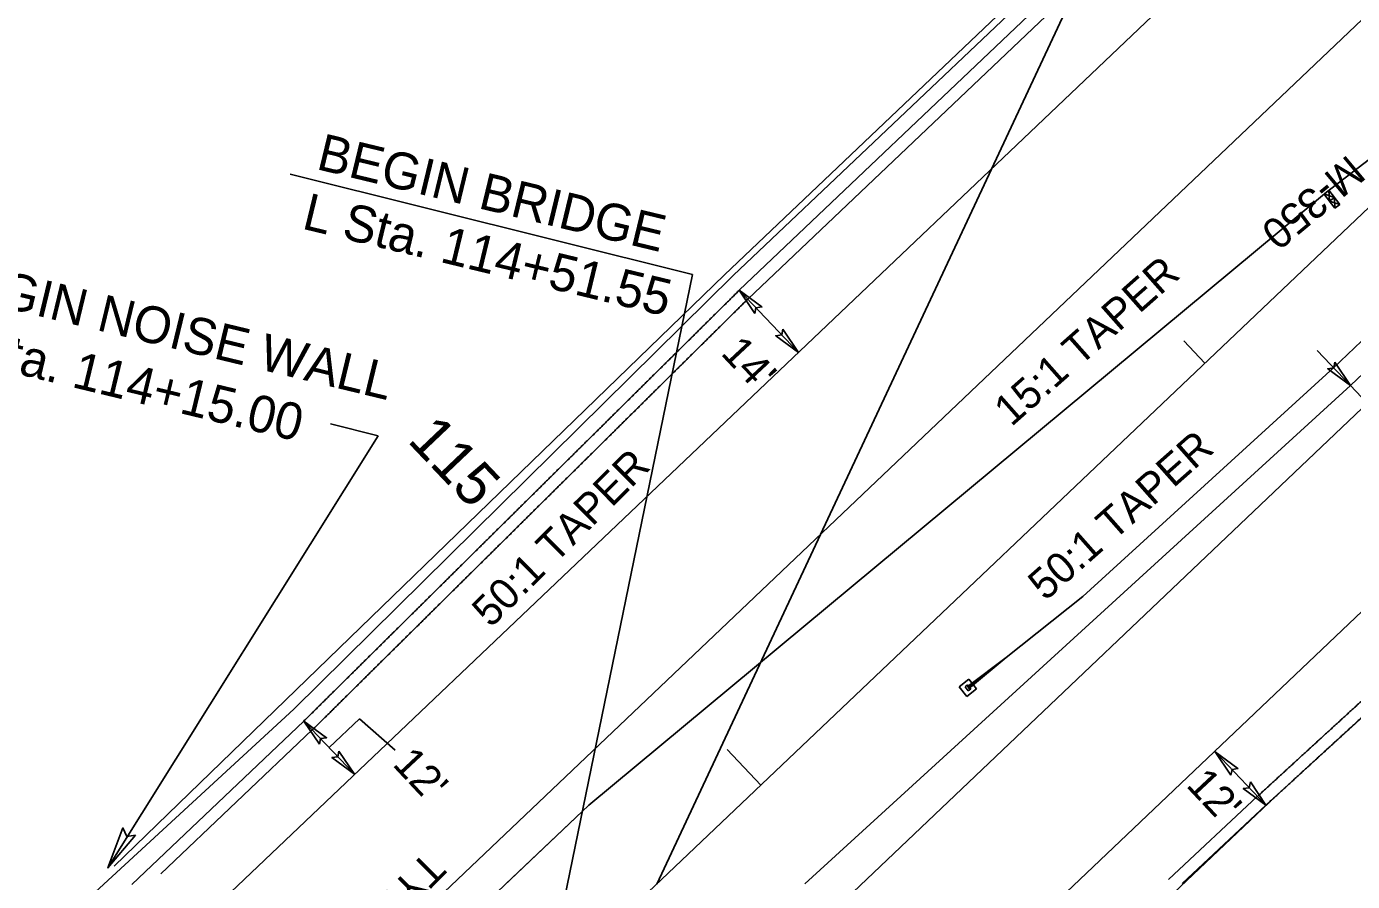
# Model space of a CAD drawing. Extents: x 2389099 to 2405615, y 552200 to 573532.
# Drawn here: x 2397828.9 to 2398045.4, y 559553.6 to 559693.2 of the extents above; entities that cross this region are included whole.
import ezdxf

# ---------------------------------------------------------------- set-up
doc = ezdxf.new("R2010")
doc.units = 0
for name, color, linetype in [('Old_Level_11', 7, 'Continuous'), ('Prop Cable Guiderail Anchor Unit CELL', 7, 'Continuous'), ('Prop Cable Guiderail Double Face', 7, 'Continuous'), ('Prop Conc Barrier Precast Reinforced Single Face', 7, 'Continuous'), ('Prop Conc Expressway Gutter', 7, 'Continuous'), ('Prop Dimension', 7, 'Continuous'), ('Prop Dimension Text', 7, 'Continuous'), ('Prop EOT', 7, 'Continuous'), ('Prop GRAU M350 Approach CELL', 7, 'Continuous'), ('Prop Guardrail', 7, 'Continuous'), ('Prop Horizontal Alignment', 7, 'Continuous'), ('Prop Horizontal Alignment Curve and Spiral Data', 7, 'Continuous'), ('Prop Horizontal Alignment Tick Large', 7, 'Continuous'), ('Prop Horizontal Alignment Tick Small', 7, 'Continuous'), ('Prop Lane Lines', 7, 'Continuous'), ('Prop Noise Wall', 7, 'Continuous')]:
    doc.layers.add(name, color=color, linetype=linetype)

# ---------------------------------------------------------------- blocks, each defined once
blk = doc.blocks.new('TERM')
at = {"layer": 'Old_Level_11'}
blk.add_lwpolyline([(-0.01375, 0.00225), (0, 0), (-0.01375, -0.0025), (-0.012, 0)], close=True, dxfattribs=at)

msp = doc.modelspace()

# ---------------------------------------------------------------- linework, layer by layer
at = {"layer": 'Prop Cable Guiderail Anchor Unit CELL'}
for p, q in [((2398001.36, 559600.11), (2397988.84, 559590.16)), ((2397988.84, 559590.16), (2397982.46, 559585.36)), ((2397988.84, 559590.16), (2397982.57, 559585.18)), ((2397988.84, 559590.16), (2397982.69, 559585.03)), ((2397988.84, 559590.16), (2397988.84, 559590.16)), ((2397981.17, 559585.34), (2397982.73, 559586.59)), ((2397983.98, 559585.02), (2397982.73, 559586.59)), ((2397982.41, 559583.78), (2397981.17, 559585.34)), ((2397982.12, 559585.35), (2397982.51, 559585.66)), ((2397982.64, 559584.7), (2397982.12, 559585.35)), ((2397982.41, 559583.78), (2397983.98, 559585.02)), ((2397983.03, 559585.01), (2397982.51, 559585.66)), ((2397982.64, 559584.7), (2397983.03, 559585.01))]:
    msp.add_line(p, q, dxfattribs=at)
at = {"layer": 'Prop Cable Guiderail Double Face'}
for p, q in [((2398042.26, 559637.46), (2398085.41, 559678.49)), ((2398001.36, 559600.11), (2398042.32, 559637.52))]:
    msp.add_line(p, q, dxfattribs=at)
at = {"layer": 'Prop Conc Barrier Precast Reinforced Single Face'}
for p, q in [((2397944.28, 559652.51), (2398828.89, 560492.26)), ((2397872.55, 559581.72), (2397944.28, 559652.51)), ((2397824.8, 559537.74), (2397872.55, 559581.72))]:
    msp.add_line(p, q, dxfattribs=at)
at = {"layer": 'Prop Conc Expressway Gutter'}
for p, q in [((2397946.63, 559648.66), (2398491.55, 560166.72)), ((2397875.55, 559578.32), (2397850.83, 559554.82)), ((2398029.88, 559567.49), (2398015.3, 559553.9))]:
    msp.add_line(p, q, dxfattribs=at)
for points in [[(2397911.12, 559613.52), (2397911.61, 559614), (2397912.08, 559614.47), (2397912.57, 559614.95), (2397913.04, 559615.42), (2397913.53, 559615.9), (2397914, 559616.37), (2397914.49, 559616.85), (2397914.97, 559617.33), (2397915.45, 559617.8), (2397915.93, 559618.28), (2397916.41, 559618.75), (2397916.89, 559619.23), (2397917.37, 559619.7), (2397917.85, 559620.18), (2397918.33, 559620.65), (2397918.81, 559621.13), (2397919.29, 559621.6), (2397919.77, 559622.08), (2397920.25, 559622.55), (2397920.73, 559623.02), (2397921.21, 559623.5), (2397921.69, 559623.97), (2397922.17, 559624.45), (2397922.66, 559624.93), (2397923.13, 559625.4), (2397923.62, 559625.88), (2397924.09, 559626.35), (2397924.58, 559626.83), (2397925.05, 559627.3), (2397925.53, 559627.78), (2397926.02, 559628.26), (2397926.49, 559628.73), (2397926.98, 559629.21), (2397927.45, 559629.68), (2397927.94, 559630.16), (2397928.41, 559630.63), (2397928.9, 559631.11), (2397929.38, 559631.59), (2397929.86, 559632.06), (2397930.34, 559632.54), (2397930.82, 559633.01), (2397931.3, 559633.49), (2397931.78, 559633.96), (2397932.26, 559634.44), (2397932.74, 559634.91), (2397933.22, 559635.39), (2397933.7, 559635.86), (2397934.18, 559636.34), (2397934.66, 559636.81), (2397935.14, 559637.29), (2397935.62, 559637.76), (2397936.11, 559638.24), (2397936.58, 559638.71), (2397937.07, 559639.19), (2397937.54, 559639.66), (2397938.03, 559640.14), (2397938.5, 559640.61), (2397938.99, 559641.09), (2397939.46, 559641.56), (2397939.95, 559642.04), (2397940.43, 559642.52), (2397940.91, 559642.99), (2397941.39, 559643.47), (2397941.87, 559643.94), (2397942.35, 559644.42), (2397942.83, 559644.89), (2397943.31, 559645.37), (2397943.79, 559645.85), (2397944.27, 559646.32), (2397944.75, 559646.8), (2397945.23, 559647.27), (2397945.71, 559647.75), (2397946.67, 559648.7)], [(2397875.58, 559578.34), (2397876.06, 559578.82), (2397876.54, 559579.29), (2397877.02, 559579.77), (2397877.5, 559580.24), (2397877.98, 559580.72), (2397878.46, 559581.19), (2397878.94, 559581.67), (2397879.42, 559582.15), (2397879.9, 559582.62), (2397880.38, 559583.1), (2397880.86, 559583.57), (2397881.34, 559584.05), (2397881.82, 559584.52), (2397882.3, 559585), (2397882.79, 559585.48), (2397883.26, 559585.95), (2397883.74, 559586.43), (2397884.22, 559586.9), (2397884.7, 559587.38), (2397885.18, 559587.85), (2397885.66, 559588.33), (2397886.14, 559588.8), (2397886.62, 559589.28), (2397887.11, 559589.76), (2397887.58, 559590.23), (2397888.07, 559590.71), (2397888.54, 559591.18), (2397889.03, 559591.66), (2397889.5, 559592.13), (2397889.99, 559592.6), (2397890.47, 559593.08), (2397890.95, 559593.55), (2397891.43, 559594.03), (2397891.91, 559594.5), (2397892.39, 559594.98), (2397892.87, 559595.45), (2397893.35, 559595.93), (2397893.83, 559596.41), (2397894.31, 559596.88), (2397894.79, 559597.36), (2397895.27, 559597.83), (2397895.75, 559598.31), (2397896.23, 559598.78), (2397896.71, 559599.26), (2397897.2, 559599.74), (2397897.67, 559600.21), (2397898.16, 559600.69), (2397898.63, 559601.16), (2397899.12, 559601.64), (2397899.59, 559602.11), (2397900.08, 559602.59), (2397900.56, 559603.07), (2397901.04, 559603.54), (2397901.52, 559604.02), (2397902, 559604.49), (2397902.48, 559604.97), (2397902.96, 559605.44), (2397903.44, 559605.92), (2397903.91, 559606.39), (2397904.4, 559606.86), (2397904.88, 559607.34), (2397905.36, 559607.81), (2397905.84, 559608.29), (2397906.32, 559608.76), (2397906.8, 559609.24), (2397907.28, 559609.71), (2397907.76, 559610.19), (2397908.24, 559610.67), (2397908.72, 559611.14), (2397909.2, 559611.62), (2397909.68, 559612.09), (2397910.16, 559612.57), (2397910.64, 559613.04), (2397911.12, 559613.52)], [(2398029.89, 559567.5), (2398030.39, 559567.96), (2398030.88, 559568.41), (2398031.39, 559568.87), (2398031.88, 559569.33), (2398032.38, 559569.79), (2398032.88, 559570.24), (2398033.38, 559570.7), (2398033.88, 559571.16), (2398034.37, 559571.61), (2398034.87, 559572.07), (2398035.37, 559572.52), (2398035.87, 559572.98), (2398036.36, 559573.44), (2398036.86, 559573.9), (2398037.36, 559574.36), (2398037.86, 559574.81), (2398038.36, 559575.27), (2398038.85, 559575.72), (2398039.36, 559576.18), (2398039.85, 559576.63), (2398040.35, 559577.09), (2398040.84, 559577.55), (2398041.35, 559578), (2398041.85, 559578.46), (2398042.34, 559578.92), (2398042.84, 559579.38), (2398043.34, 559579.83), (2398043.84, 559580.29), (2398044.33, 559580.74), (2398044.83, 559581.2), (2398045.33, 559581.66), (2398045.83, 559582.11), (2398046.33, 559582.57), (2398046.82, 559583.03), (2398047.33, 559583.49), (2398047.82, 559583.94), (2398048.32, 559584.4), (2398048.82, 559584.86), (2398049.32, 559585.31), (2398049.82, 559585.77), (2398050.31, 559586.22), (2398050.81, 559586.68), (2398051.31, 559587.14), (2398051.81, 559587.6), (2398052.31, 559588.05), (2398052.8, 559588.51), (2398053.3, 559588.97), (2398053.8, 559589.42), (2398054.3, 559589.88), (2398054.79, 559590.33), (2398055.3, 559590.79), (2398055.8, 559591.25), (2398056.29, 559591.7), (2398056.79, 559592.16), (2398057.29, 559592.62), (2398057.79, 559593.08), (2398058.28, 559593.53), (2398058.78, 559593.99), (2398059.28, 559594.44), (2398059.78, 559594.9), (2398060.28, 559595.36), (2398060.77, 559595.81), (2398061.27, 559596.27), (2398061.77, 559596.73), (2398062.27, 559597.19), (2398062.76, 559597.64), (2398063.26, 559598.1), (2398063.77, 559598.56), (2398064.26, 559599.01), (2398064.76, 559599.47), (2398065.26, 559599.92), (2398065.76, 559600.38), (2398066.25, 559600.84), (2398066.75, 559601.29)]]:
    msp.add_spline(points, degree=3, dxfattribs=at)
at = {"layer": 'Prop Dimension'}
for p, q in [((2397931.78, 559553.13), (2398012.75, 559726.19)), ((2397937.64, 559652.66), (2397871.95, 559669.08)), ((2397913.68, 559535.92), (2397937.64, 559652.66)), ((2397954.9, 559639.96), (2397945.25, 559650.11)), ((2398039.58, 559640.28), (2398045.01, 559634.57)), ((2398045.01, 559634.57), (2398047.77, 559631.67)), ((2397878.52, 559628.28), (2397886.31, 559626.33)), ((2397886.31, 559626.33), (2397842.18, 559555.78)), ((2397882.44, 559571.07), (2397874.17, 559579.77)), ((2397883.24, 559580.11), (2397878.29, 559575.43)), ((2397889.06, 559575.02), (2397883.24, 559580.11)), ((2398031.24, 559566.03), (2398022.97, 559574.73))]:
    msp.add_line(p, q, dxfattribs=at)
for points in [[(2397947.79, 559646.31), (2397945.25, 559650.11), (2397948.95, 559647.38), (2397947.98, 559647.24)], [(2397952.36, 559643.76), (2397954.9, 559639.96), (2397951.2, 559642.69), (2397952.18, 559642.82)], [(2398042.47, 559638.36), (2398045.01, 559634.57), (2398041.32, 559637.29), (2398042.29, 559637.43)], [(2397876.71, 559575.97), (2397874.17, 559579.77), (2397877.87, 559577.04), (2397876.89, 559576.9)], [(2397879.9, 559574.86), (2397882.44, 559571.07), (2397878.74, 559573.8), (2397879.71, 559573.93)], [(2398025.51, 559570.93), (2398022.97, 559574.73), (2398026.67, 559572), (2398025.7, 559571.86)], [(2398028.7, 559569.82), (2398031.24, 559566.03), (2398027.54, 559568.76), (2398028.52, 559568.89)]]:
    msp.add_lwpolyline(points, close=True, dxfattribs=at)
at = {"layer": 'Prop EOT'}
for p, q in [((2397075.71, 558804.1), (2398839.56, 560481.03)), ((2397092.24, 558786.7), (2398856.1, 560463.63)), ((2398045.01, 559634.57), (2398885.04, 560433.19)), ((2397732.72, 559332.14), (2398887.8, 560430.29)), ((2397749.26, 559314.75), (2398904.33, 560412.9)), ((2397945.25, 559650.11), (2398525.64, 560201.89)), ((2398041.1, 559666.14), (2398071.06, 559689.11)), ((2397920.68, 559566.03), (2398041.1, 559666.14)), ((2397955.93, 559553.19), (2398045.01, 559634.57)), ((2397874.17, 559579.77), (2397846.1, 559553.08)), ((2397907.09, 559553.11), (2397920.68, 559566.03)), ((2398031.24, 559566.03), (2398017.53, 559553.24))]:
    msp.add_line(p, q, dxfattribs=at)
for points in [[(2397909.72, 559614.94), (2397910.2, 559615.42), (2397910.68, 559615.89), (2397911.16, 559616.37), (2397911.64, 559616.84), (2397912.12, 559617.32), (2397912.6, 559617.79), (2397913.08, 559618.27), (2397913.56, 559618.75), (2397914.04, 559619.22), (2397914.52, 559619.7), (2397915, 559620.17), (2397915.48, 559620.65), (2397915.96, 559621.12), (2397916.44, 559621.6), (2397916.93, 559622.08), (2397917.4, 559622.55), (2397917.89, 559623.03), (2397918.36, 559623.5), (2397918.85, 559623.98), (2397919.32, 559624.45), (2397919.81, 559624.92), (2397920.28, 559625.4), (2397920.77, 559625.87), (2397921.25, 559626.35), (2397921.73, 559626.82), (2397922.21, 559627.3), (2397922.69, 559627.77), (2397923.17, 559628.25), (2397923.64, 559628.72), (2397924.13, 559629.2), (2397924.61, 559629.68), (2397925.09, 559630.15), (2397925.57, 559630.63), (2397926.05, 559631.1), (2397926.53, 559631.58), (2397927.01, 559632.05), (2397927.49, 559632.53), (2397927.97, 559633.01), (2397928.45, 559633.48), (2397928.93, 559633.96), (2397929.41, 559634.43), (2397929.89, 559634.91), (2397930.37, 559635.38), (2397930.85, 559635.86), (2397931.34, 559636.34), (2397931.81, 559636.81), (2397932.3, 559637.29), (2397932.77, 559637.76), (2397933.26, 559638.24), (2397933.73, 559638.71), (2397934.22, 559639.19), (2397934.7, 559639.66), (2397935.18, 559640.13), (2397935.66, 559640.61), (2397936.14, 559641.08), (2397936.62, 559641.56), (2397937.1, 559642.03), (2397937.58, 559642.51), (2397938.06, 559642.98), (2397938.54, 559643.46), (2397939.02, 559643.94), (2397939.5, 559644.41), (2397939.98, 559644.89), (2397940.46, 559645.36), (2397940.94, 559645.84), (2397941.42, 559646.31), (2397941.9, 559646.79), (2397942.39, 559647.27), (2397942.86, 559647.74), (2397943.35, 559648.22), (2397943.82, 559648.69), (2397944.31, 559649.17), (2397945.27, 559650.12)], [(2397874.17, 559579.77), (2397874.65, 559580.24), (2397875.13, 559580.72), (2397875.61, 559581.19), (2397876.09, 559581.67), (2397876.57, 559582.14), (2397877.05, 559582.62), (2397877.53, 559583.09), (2397878.02, 559583.57), (2397878.49, 559584.04), (2397878.98, 559584.52), (2397879.45, 559584.99), (2397879.94, 559585.47), (2397880.41, 559585.94), (2397880.89, 559586.42), (2397881.38, 559586.9), (2397881.85, 559587.37), (2397882.34, 559587.85), (2397882.81, 559588.32), (2397883.3, 559588.8), (2397883.77, 559589.27), (2397884.26, 559589.75), (2397884.73, 559590.22), (2397885.22, 559590.7), (2397885.7, 559591.18), (2397886.18, 559591.65), (2397886.66, 559592.13), (2397887.14, 559592.6), (2397887.62, 559593.08), (2397888.1, 559593.55), (2397888.58, 559594.03), (2397889.06, 559594.5), (2397889.54, 559594.98), (2397890.02, 559595.45), (2397890.5, 559595.93), (2397890.98, 559596.4), (2397891.46, 559596.88), (2397891.94, 559597.35), (2397892.43, 559597.83), (2397892.9, 559598.3), (2397893.39, 559598.78), (2397893.86, 559599.25), (2397894.35, 559599.73), (2397894.82, 559600.2), (2397895.31, 559600.68), (2397895.79, 559601.16), (2397896.27, 559601.63), (2397896.75, 559602.11), (2397897.23, 559602.58), (2397897.71, 559603.06), (2397898.19, 559603.53), (2397898.67, 559604.01), (2397899.15, 559604.49), (2397899.63, 559604.96), (2397900.11, 559605.44), (2397900.59, 559605.91), (2397901.07, 559606.39), (2397901.55, 559606.86), (2397902.03, 559607.34), (2397902.51, 559607.81), (2397902.99, 559608.29), (2397903.48, 559608.77), (2397903.95, 559609.24), (2397904.43, 559609.71), (2397904.91, 559610.19), (2397905.39, 559610.66), (2397905.87, 559611.14), (2397906.35, 559611.61), (2397906.84, 559612.09), (2397907.31, 559612.56), (2397907.8, 559613.04), (2397908.27, 559613.51), (2397908.76, 559613.99), (2397909.23, 559614.46), (2397909.72, 559614.94)], [(2398031.24, 559566.03), (2398031.74, 559566.49), (2398032.24, 559566.94), (2398032.74, 559567.4), (2398033.23, 559567.85), (2398033.73, 559568.31), (2398034.23, 559568.77), (2398034.73, 559569.22), (2398035.23, 559569.68), (2398035.72, 559570.14), (2398036.22, 559570.6), (2398036.72, 559571.05), (2398037.22, 559571.51), (2398037.71, 559571.96), (2398038.22, 559572.42), (2398038.72, 559572.88), (2398039.21, 559573.33), (2398039.71, 559573.79), (2398040.21, 559574.25), (2398040.71, 559574.71), (2398041.2, 559575.16), (2398041.7, 559575.62), (2398042.2, 559576.07), (2398042.7, 559576.53), (2398043.2, 559576.99), (2398043.69, 559577.44), (2398044.19, 559577.9), (2398044.69, 559578.36), (2398045.19, 559578.82), (2398045.68, 559579.27), (2398046.18, 559579.73), (2398046.69, 559580.19), (2398047.18, 559580.64), (2398047.68, 559581.1), (2398048.18, 559581.55), (2398048.68, 559582.01), (2398049.17, 559582.46), (2398049.67, 559582.92), (2398050.17, 559583.38), (2398050.67, 559583.84), (2398051.17, 559584.3), (2398051.66, 559584.75), (2398052.16, 559585.21), (2398052.66, 559585.66), (2398053.16, 559586.12), (2398053.66, 559586.58), (2398054.15, 559587.03), (2398054.66, 559587.49), (2398055.15, 559587.95), (2398055.65, 559588.41), (2398056.15, 559588.86), (2398056.65, 559589.32), (2398057.15, 559589.78), (2398057.64, 559590.23), (2398058.14, 559590.69), (2398058.64, 559591.14), (2398059.14, 559591.6), (2398059.63, 559592.05), (2398060.13, 559592.51), (2398060.63, 559592.97), (2398061.13, 559593.43), (2398061.63, 559593.89), (2398062.12, 559594.34), (2398062.63, 559594.8), (2398063.12, 559595.25), (2398063.62, 559595.71), (2398064.12, 559596.16), (2398064.62, 559596.62), (2398065.12, 559597.08), (2398065.61, 559597.54), (2398066.11, 559598), (2398066.61, 559598.45), (2398067.11, 559598.91), (2398067.6, 559599.36), (2398068.1, 559599.82)]]:
    msp.add_spline(points, degree=3, dxfattribs=at)
at = {"layer": 'Prop GRAU M350 Approach CELL'}
for p, q in [((2398041.1, 559666.14), (2398071.06, 559689.11)), ((2398041.5, 559666.44), (2398043.29, 559664.11)), ((2398041.62, 559664.64), (2398041.5, 559666.44)), ((2398040.71, 559665.83), (2398042.49, 559663.5)), ((2398040.71, 559665.83), (2398042.41, 559665.25)), ((2398041.62, 559664.64), (2398042.41, 559665.25)), ((2398043.29, 559664.11), (2398041.62, 559664.64)), ((2398042.41, 559665.25), (2398042.49, 559663.5)), ((2398042.49, 559663.5), (2398043.29, 559664.11))]:
    msp.add_line(p, q, dxfattribs=at)
at = {"layer": 'Prop Guardrail'}
for p, q in [((2397920.68, 559566.03), (2398041.1, 559666.14)), ((2398031.24, 559566.03), (2398058.87, 559591.33)), ((2398013.12, 559548.8), (2398032.74, 559567.4)), ((2397902.56, 559548.81), (2397920.68, 559566.03))]:
    msp.add_line(p, q, dxfattribs=at)
at = {"layer": 'Prop Horizontal Alignment'}
msp.add_line((2396449.76, 558144.15), (2398871.95, 560446.96), dxfattribs=at)
at = {"layer": 'Prop Horizontal Alignment Tick Large'}
msp.add_line((2397948.79, 559569.3), (2397943.28, 559575.1), dxfattribs=at)
at = {"layer": 'Prop Horizontal Alignment Tick Small'}
msp.add_line((2398021.26, 559638.2), (2398017.82, 559641.83), dxfattribs=at)
at = {"layer": 'Prop Lane Lines'}
msp.add_line((2397075.71, 558804.1), (2398839.56, 560481.03), dxfattribs=at)
at = {"layer": 'Prop Noise Wall'}
for p, q in [((2397942.84, 559652.64), (2398827.51, 560493.71)), ((2397843.18, 559556.09), (2397942.84, 559652.64))]:
    msp.add_line(p, q, dxfattribs=at)

# ---------------------------------------------------------------- block references
at = {"layer": 'Prop Dimension', "xscale": 500.00000000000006, "yscale": 500.00000000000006, "rotation": -120.82035739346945}
msp.add_blockref('TERM', (2397842.18, 559555.78), dxfattribs=at)

# ---------------------------------------------------------------- texts
at = {"layer": 'Old_Level_11'}
for s, p in [('BEGIN BRIDGE', (2397876.02, 559669.93)), ('L Sta. 114+51.55', (2397873.67, 559660.21))]:
    msp.add_text(s, height=6, rotation=346.4323, dxfattribs=at).set_placement(p)
at = {"layer": 'Prop Dimension Text'}
for s, height, rotation, p in [('M-350', 5, 219.7795, (2398044.66, 559672.39)), ('BEGIN NOISE WALL', 6, 346.4323, (2397813.72, 559650.03)), ('15:1 TAPER', 5, 41.4787, (2397989.66, 559627.72)), (' L Sta. 114+15.00', 6, 346.4323, (2397811.38, 559640.31)), ("14'", 5, 313.1053, (2397942.09, 559639.72)), ('50:1 TAPER', 5, 41.4787, (2397995.21, 559599.25)), ('50:1 TAPER', 5, 44.9343, (2397904.68, 559594.86)), ("12'", 5, 313.1053, (2397888.49, 559572.6)), ("12'", 5, 313.1053, (2398018.05, 559569.19)), ('TYPE B-77', 5, 225.0612, (2397894.15, 559558.7))]:
    msp.add_text(s, height=height, rotation=rotation, dxfattribs=at).set_placement(p)
at = {"layer": 'Prop Horizontal Alignment Curve and Spiral Data'}
msp.add_text('115', height=7, rotation=313.5528, dxfattribs=at).set_placement((2397890.92, 559625.48))

doc.saveas('drawing.dxf')
